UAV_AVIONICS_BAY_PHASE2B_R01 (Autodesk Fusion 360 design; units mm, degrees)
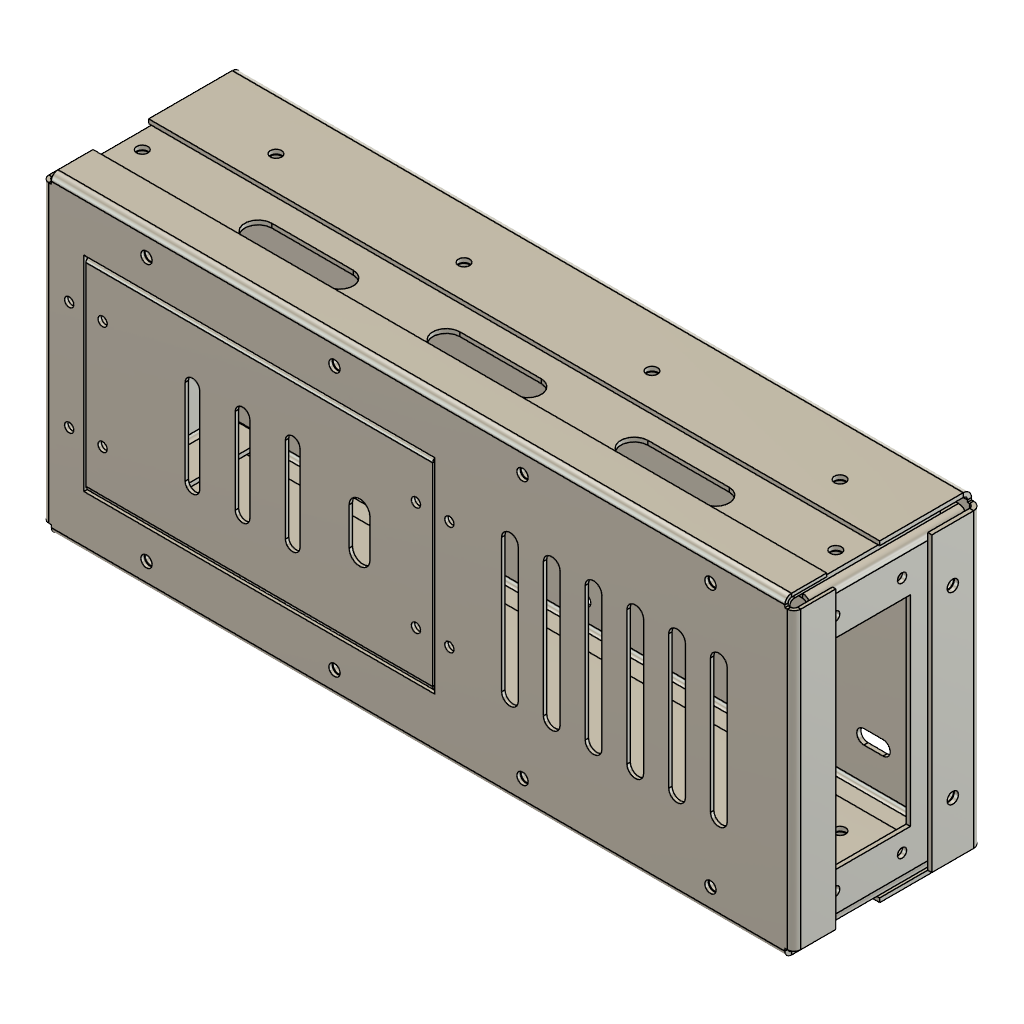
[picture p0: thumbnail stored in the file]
part number: 2026-11-23-23-53-07-860
part number: 2026-11-23-23-53-08-084
part number: 2026-11-23-23-53-08-095
part number: 2026-11-23-23-53-08-107
part number: 2026-11-23-23-53-08-119
part number: 2026-11-23-23-53-08-137
part number: 2026-11-23-23-53-08-150
part number: 2026-11-23-23-53-08-161
part number: 2026-11-23-23-53-08-171
part number: 2026-11-23-23-53-08-219
part number: 2026-11-23-23-53-09-132
part number: 2026-11-23-23-53-09-607
part number: 2026-11-23-23-53-10-129
part number: 2026-11-23-23-53-10-727
part number: 2026-11-23-23-53-11-436
part number: 2026-11-23-23-53-12-534
part number: 2026-11-23-23-53-13-223
parameter "BAY_LENGTH" = 180 comment "[Assumption] Concept avionics bay overall outer length (X)"
parameter "BAY_WIDTH" = 75 comment "[Assumption] Concept avionics bay overall outer width (Y)"
parameter "BAY_HEIGHT" = 45 comment "[Assumption] Concept avionics bay overall outer height (Z)"
parameter "TRAY_FLANGE_H" = 22 comment "[Preliminary] Base tray perimeter upward flange height"
parameter "COVER_SKIRT_H" = 10 comment "[Preliminary] Top cover downward perimeter skirt height"
parameter "FORWARD_ZONE_END_X" = 95 comment "[Preliminary] X-boundary separating battery zone and aft deck"
parameter "HATCH_LENGTH" = 92 comment "[Preliminary] Service access hatch opening length"
parameter "HATCH_WIDTH" = 54 comment "[Preliminary] Service access hatch opening width"
parameter "T_BASE_TRAY" = 1 comment "[Preliminary] Main folded base tray thickness"
parameter "T_TOP_COVER" = 0.8 comment "[Preliminary] Removable top cover thickness"
parameter "T_ACCESS_HATCH" = 0.8 comment "[Preliminary] Service access hatch thickness"
parameter "T_SIDE_RAIL" = 1 comment "[Preliminary] Left and right side support rails thickness"
parameter "T_BULKHEAD" = 1 comment "[Preliminary] Front, rear, and connector bulkheads thickness"
parameter "T_EQUIP_DECK" = 1 comment "[Preliminary] Removable internal equipment deck thickness"
parameter "T_BRACKET" = 1 comment "[Preliminary] Structural and retention brackets thickness"
parameter "T_CABLE_CH" = 0.8 comment "[Preliminary] Cable routing channel and clamp thickness"
parameter "BEND_R_1_0" = 1 comment "[Preliminary] Inside bend radius for 1.0 mm Al 5052-H32"
parameter "BEND_R_0_8" = 0.8 comment "[Preliminary] Inside bend radius for 0.8 mm Al 5052-H32"
parameter "RELIEF_W_1_0" = 1.5 comment "[Preliminary] Bend relief width for 1.0 mm sheet"
parameter "RELIEF_D_1_0" = 2.5 comment "[Preliminary] Bend relief depth for 1.0 mm sheet"
parameter "RELIEF_W_0_8" = 1.2 comment "[Preliminary] Bend relief width for 0.8 mm sheet"
parameter "RELIEF_D_0_8" = 2.1 comment "[Preliminary] Bend relief depth for 0.8 mm sheet"
parameter "HOLE_CLR_M2_0" = 2.2 comment "[Preliminary] M2.0 medium clearance hole diameter"
parameter "HOLE_CLR_M2_5" = 2.7 comment "[Preliminary] M2.5 medium clearance hole diameter"
parameter "HOLE_CLR_M3_0" = 3.4 comment "[Preliminary] M3.0 medium clearance hole diameter"
parameter "HEAD_DIA_M2_0" = 3.8 comment "[Preliminary] ISO 4762/7380 M2.0 head diameter"
parameter "HEAD_DIA_M2_5" = 4.5 comment "[Preliminary] ISO 4762/7380 M2.5 head diameter"
parameter "STANDOFF_DECK_H" = 6 comment "[Preliminary] Under-deck plenum standoff height"
parameter "STANDOFF_PCB_H" = 4 comment "[Preliminary] PCB mounting standoff height"
parameter "ISO_PAD_THICK" = 2 comment "[Preliminary] Battery elastomer isolation pad thickness"
parameter "CLR_EQUIP_WALL" = 2 comment "[Preliminary] Minimum clearance between electronics and walls"
parameter "CLR_COMPONENT" = 1.5 comment "[Preliminary] General minimum clearance between adjacent parts"
parameter "CLR_SLIP_FIT" = 0.25 comment "[Preliminary] Per-side slip clearance for nested sheet metal parts"
parameter "CLR_COVER_FIT" = 0.3 comment "[Preliminary] Per-side clearance between cover skirt and chassis"
parameter "CLR_HATCH_GAP" = 0.5 comment "[Preliminary] Perimeter gap around removable service hatch"
parameter "d37" = 2
parameter "d38" = 1
parameter "d39" = 0.8
sketch "SK_Base_Tray_Blank" plane through (0, 0, 0) normal (0, 0, 1) x axis (1, 0, 0)
  line L1 (177.5, -37.5) -> (2.5, -37.5)
  line L2 (177.5, -35) -> (177.5, -37.5)
  line L3 (180, -35) -> (177.5, -35)
  line L4 (180, 35) -> (180, -35)
  line L5 (177.5, 35) -> (180, 35)
  line L6 (177.5, 37.5) -> (177.5, 35)
  line L7 (2.5, 37.5) -> (177.5, 37.5)
  line L8 (2.5, 35) -> (2.5, 37.5)
  line L9 (0, 35) -> (2.5, 35)
  line L10 (0, -35) -> (0, 35)
  line L11 (2.5, -35) -> (0, -35)
  line L12 (2.5, -37.5) -> (2.5, -35)
face "BaseFlange1" sketch "SK_Base_Tray_Blank"
face "EdgeFlange2" FlangeHeight 22 FlangeAngle 90
face "EdgeFlange3" FlangeHeight 12 FlangeAngle 90
sketch "SK_Base_Tray_Floor_Cutouts" plane through (0, 0, 0) normal (0, 0, 1) x axis (1, 0, 0)
  line L1 (27.3, -24.3) -> (22.7, -24.3)
  line L2 (22.7, -27.7) -> (27.3, -27.7)
  line L3 (27.3, 27.7) -> (22.7, 27.7)
  line L4 (22.7, 24.3) -> (27.3, 24.3)
  line L5 (157.3, -24.3) -> (152.7, -24.3)
  line L6 (152.7, -27.7) -> (157.3, -27.7)
  line L7 (157.3, 27.7) -> (152.7, 27.7)
  line L8 (152.7, 24.3) -> (157.3, 24.3)
  line L9 (64.5, -11.5) -> (35.5, -11.5)
  line L10 (35.5, -18.5) -> (64.5, -18.5)
  line L11 (149.5, 3.5) -> (120.5, 3.5)
  line L12 (120.5, -3.5) -> (149.5, -3.5)
  arc A1 centre (27.3, -26) radius 1.7 clockwise from (27.3, -24.3) to (27.3, -27.7)
  arc A2 centre (22.7, -26) radius 1.7 clockwise from (22.7, -27.7) to (22.7, -24.3)
  arc A3 centre (27.3, 26) radius 1.7 clockwise from (27.3, 27.7) to (27.3, 24.3)
  arc A4 centre (22.7, 26) radius 1.7 clockwise from (22.7, 24.3) to (22.7, 27.7)
  arc A5 centre (157.3, -26) radius 1.7 clockwise from (157.3, -24.3) to (157.3, -27.7)
  arc A6 centre (152.7, -26) radius 1.7 clockwise from (152.7, -27.7) to (152.7, -24.3)
  arc A7 centre (157.3, 26) radius 1.7 clockwise from (157.3, 27.7) to (157.3, 24.3)
  arc A8 centre (152.7, 26) radius 1.7 clockwise from (152.7, 24.3) to (152.7, 27.7)
  circle C1 centre (102, -28.5) radius 1.35
  circle C2 centre (102, 28.5) radius 1.35
  circle C3 centre (168, -28.5) radius 1.35
  circle C4 centre (168, 28.5) radius 1.35
  circle C5 centre (14, -31) radius 1.35
  circle C6 centre (14, 1) radius 1.35
  circle C7 centre (86, -31) radius 1.35
  circle C8 centre (86, 1) radius 1.35
  circle C9 centre (13, 11) radius 1.1
  circle C10 centre (13, 27) radius 1.1
  circle C11 centre (45, 11) radius 1.1
  circle C12 centre (45, 27) radius 1.1
  circle C13 centre (57, 11) radius 1.1
  circle C14 centre (57, 27) radius 1.1
  circle C15 centre (85, 11) radius 1.1
  circle C16 centre (85, 27) radius 1.1
  arc A9 centre (64.5, -15) radius 3.5 clockwise from (64.5, -11.5) to (64.5, -18.5)
  arc A10 centre (35.5, -15) radius 3.5 clockwise from (35.5, -18.5) to (35.5, -11.5)
  arc A11 centre (149.5, 0) radius 3.5 clockwise from (149.5, 3.5) to (149.5, -3.5)
  arc A12 centre (120.5, 0) radius 3.5 clockwise from (120.5, -3.5) to (120.5, 3.5)
extrude "Extrude1" cut sketch "SK_Base_Tray_Floor_Cutouts" distance 2
work_plane "WorkPlane1" AlongDistance -37.5 ExtraOffset 0
sketch "SK_Tray_Left_Wall_Holes" plane through (0, -37.5, 0) normal (0, 1, 0) x axis (1, 0, 0)
  circle C1 centre (25, -14) radius 1.35
  circle C2 centre (70, -14) radius 1.35
  circle C3 centre (115, -14) radius 1.35
  circle C4 centre (160, -14) radius 1.35
extrude "Extrude2" cut sketch "SK_Tray_Left_Wall_Holes" distance 2
work_plane "WorkPlane2" AlongDistance 37.5 ExtraOffset 0
sketch "SK_Tray_Right_Wall_Holes" plane through (0, 37.5, 0) normal (0, 1, 0) x axis (1, 0, 0)
  circle C1 centre (25, -14) radius 1.35
  circle C2 centre (70, -14) radius 1.35
  circle C3 centre (115, -14) radius 1.35
  circle C4 centre (160, -14) radius 1.35
extrude "Extrude3" cut sketch "SK_Tray_Right_Wall_Holes" distance 2
sketch "SK_Tray_Front_Lip_Holes" plane through (0, 0, 0) normal (1, 0, 0) x axis (0, 0, -1)
  circle C1 centre (-7, -22) radius 1.35
  circle C2 centre (-7, 22) radius 1.35
extrude "Extrude4" cut sketch "SK_Tray_Front_Lip_Holes" distance 2
work_plane "WorkPlane3" AlongDistance 180 ExtraOffset 0
sketch "SK_Tray_Rear_Lip_Holes" plane through (180, 0, 0) normal (1, 0, 0) x axis (0, 0, -1)
  circle C1 centre (-7, -22) radius 1.35
  circle C2 centre (-7, 22) radius 1.35
extrude "Extrude5" cut sketch "SK_Tray_Rear_Lip_Holes" distance 2
work_plane "WorkPlane1" AlongDistance -36.35 ExtraOffset 0
sketch "SK_PDB-01-102_Left_Side_Rail_Web" plane through (0, -36.35, 0) normal (0, 1, 0) x axis (1, 0, 0)
  line L1 (177, -7) -> (3, -7)
  line L2 (177, -44) -> (177, -7)
  line L3 (3, -44) -> (177, -44)
  line L4 (3, -7) -> (3, -44)
face "BaseFlange1" sketch "SK_PDB-01-102_Left_Side_Rail_Web"
face "EdgeFlange2" FlangeHeight 9 FlangeAngle 90
sketch "SK_PDB-01-102_Left_Side_Rail_Web_Features" plane through (0, -36.35, 0) normal (0, 1, 0) x axis (1, 0, 0)
  line L1 (57.25, -34.25) -> (37.75, -34.25)
  line L2 (37.75, -27.75) -> (57.25, -27.75)
  line L3 (102.25, -34.25) -> (82.75, -34.25)
  line L4 (82.75, -27.75) -> (102.25, -27.75)
  line L5 (147.25, -34.25) -> (127.75, -34.25)
  line L6 (127.75, -27.75) -> (147.25, -27.75)
  circle C1 centre (25, -14) radius 1.35
  circle C2 centre (70, -14) radius 1.35
  circle C3 centre (115, -14) radius 1.35
  circle C4 centre (160, -14) radius 1.35
  circle C5 centre (7, -28) radius 1.35
  circle C6 centre (173, -28) radius 1.35
  arc A1 centre (57.25, -31) radius 3.25 clockwise from (57.25, -27.75) to (57.25, -34.25)
  arc A2 centre (37.75, -31) radius 3.25 clockwise from (37.75, -34.25) to (37.75, -27.75)
  arc A3 centre (102.25, -31) radius 3.25 clockwise from (102.25, -27.75) to (102.25, -34.25)
  arc A4 centre (82.75, -31) radius 3.25 clockwise from (82.75, -34.25) to (82.75, -27.75)
  arc A5 centre (147.25, -31) radius 3.25 clockwise from (147.25, -27.75) to (147.25, -34.25)
  arc A6 centre (127.75, -31) radius 3.25 clockwise from (127.75, -34.25) to (127.75, -27.75)
extrude "Extrude1" cut sketch "SK_PDB-01-102_Left_Side_Rail_Web_Features" distance 2
work_plane "WorkPlane2" AlongDistance 44 ExtraOffset 0
sketch "SK_PDB-01-102_Left_Side_Rail_Top_Holes" plane through (0, 0, 44) normal (0, 0, 1) x axis (1, 0, 0)
  circle C1 centre (25, -31.5) radius 1.35
  circle C2 centre (70, -31.5) radius 1.35
  circle C3 centre (115, -31.5) radius 1.35
  circle C4 centre (160, -31.5) radius 1.35
extrude "Extrude2" cut sketch "SK_PDB-01-102_Left_Side_Rail_Top_Holes" distance 2
work_plane "WorkPlane1" AlongDistance 36.35 ExtraOffset 0
sketch "SK_PDB-01-103_Right_Side_Rail_Web" plane through (0, 36.35, 0) normal (0, 1, 0) x axis (1, 0, 0)
  line L1 (177, -7) -> (3, -7)
  line L2 (177, -44) -> (177, -7)
  line L3 (3, -44) -> (177, -44)
  line L4 (3, -7) -> (3, -44)
face "BaseFlange2" sketch "SK_PDB-01-103_Right_Side_Rail_Web"
face "EdgeFlange3" FlangeHeight 9 FlangeAngle 90
sketch "SK_PDB-01-103_Right_Side_Rail_Web_Features" plane through (0, 36.35, 0) normal (0, 1, 0) x axis (1, 0, 0)
  line L1 (57.25, -34.25) -> (37.75, -34.25)
  line L2 (37.75, -27.75) -> (57.25, -27.75)
  line L3 (102.25, -34.25) -> (82.75, -34.25)
  line L4 (82.75, -27.75) -> (102.25, -27.75)
  line L5 (147.25, -34.25) -> (127.75, -34.25)
  line L6 (127.75, -27.75) -> (147.25, -27.75)
  circle C1 centre (25, -14) radius 1.35
  circle C2 centre (70, -14) radius 1.35
  circle C3 centre (115, -14) radius 1.35
  circle C4 centre (160, -14) radius 1.35
  circle C5 centre (7, -28) radius 1.35
  circle C6 centre (173, -28) radius 1.35
  arc A1 centre (57.25, -31) radius 3.25 clockwise from (57.25, -27.75) to (57.25, -34.25)
  arc A2 centre (37.75, -31) radius 3.25 clockwise from (37.75, -34.25) to (37.75, -27.75)
  arc A3 centre (102.25, -31) radius 3.25 clockwise from (102.25, -27.75) to (102.25, -34.25)
  arc A4 centre (82.75, -31) radius 3.25 clockwise from (82.75, -34.25) to (82.75, -27.75)
  arc A5 centre (147.25, -31) radius 3.25 clockwise from (147.25, -27.75) to (147.25, -34.25)
  arc A6 centre (127.75, -31) radius 3.25 clockwise from (127.75, -34.25) to (127.75, -27.75)
extrude "Extrude1" cut sketch "SK_PDB-01-103_Right_Side_Rail_Web_Features" distance 2
work_plane "WorkPlane2" AlongDistance 44 ExtraOffset 0
sketch "SK_PDB-01-103_Right_Side_Rail_Top_Holes" plane through (0, 0, 44) normal (0, 0, 1) x axis (1, 0, 0)
  circle C1 centre (25, 31.5) radius 1.35
  circle C2 centre (70, 31.5) radius 1.35
  circle C3 centre (115, 31.5) radius 1.35
  circle C4 centre (160, 31.5) radius 1.35
extrude "Extrude2" cut sketch "SK_PDB-01-103_Right_Side_Rail_Top_Holes" distance 2
work_plane "WorkPlane1" AlongDistance 1.15 ExtraOffset 0
sketch "SK_Front_Bulkhead_Blank" plane through (1.15, 0, 0) normal (1, 0, 0) x axis (0, 0, -1)
  line L1 (-2.5, 35.2) -> (-2.5, -35.2)
  line L2 (-39.8, 35.2) -> (-2.5, 35.2)
  line L3 (-39.8, 32.2) -> (-39.8, 35.2)
  line L4 (-42.8, 32.2) -> (-39.8, 32.2)
  line L5 (-42.8, -32.2) -> (-42.8, 32.2)
  line L6 (-39.8, -32.2) -> (-42.8, -32.2)
  line L7 (-39.8, -35.2) -> (-39.8, -32.2)
  line L8 (-2.5, -35.2) -> (-39.8, -35.2)
face "BaseFlange1" sketch "SK_Front_Bulkhead_Blank"
face "EdgeFlange2" FlangeHeight 10 FlangeAngle 90
face "EdgeFlange3" FlangeHeight 8 FlangeAngle 90
sketch "SK_Front_Bulkhead_Cutouts" plane through (1.15, 0, 0) normal (1, 0, 0) x axis (0, 0, -1)
  line L1 (-26.5, -16.5) -> (-26.5, -23.5)
  line L2 (-21.5, -23.5) -> (-21.5, -16.5)
  line L3 (-26.5, 23.5) -> (-26.5, 16.5)
  line L4 (-21.5, 16.5) -> (-21.5, 23.5)
  circle C1 centre (-7, -22) radius 1.35
  circle C2 centre (-7, 22) radius 1.35
  circle C3 centre (-24, 0) radius 5
  circle C4 centre (-24, -9) radius 1.1
  circle C5 centre (-24, 9) radius 1.1
  arc A1 centre (-24, -16.5) radius 2.5 clockwise from (-26.5, -16.5) to (-21.5, -16.5)
  arc A2 centre (-24, -23.5) radius 2.5 clockwise from (-21.5, -23.5) to (-26.5, -23.5)
  arc A3 centre (-24, 23.5) radius 2.5 clockwise from (-26.5, 23.5) to (-21.5, 23.5)
  arc A4 centre (-24, 16.5) radius 2.5 clockwise from (-21.5, 16.5) to (-26.5, 16.5)
extrude "Extrude1" cut sketch "SK_Front_Bulkhead_Cutouts" distance 2
work_plane "WorkPlane2" AlongDistance -35.2 ExtraOffset 0
sketch "SK_Front_Left_Hole" plane through (0, -35.2, 0) normal (0, 1, 0) x axis (1, 0, 0)
  circle C1 centre (7, -28) radius 1.35
extrude "Extrude2" cut sketch "SK_Front_Left_Hole" distance 2
work_plane "WorkPlane3" AlongDistance 35.2 ExtraOffset 0
sketch "SK_Front_Right_Hole" plane through (0, 35.2, 0) normal (0, 1, 0) x axis (1, 0, 0)
  circle C1 centre (7, -28) radius 1.35
extrude "Extrude3" cut sketch "SK_Front_Right_Hole" distance 2
work_plane "WorkPlane1" AlongDistance 178.85 ExtraOffset 0
sketch "SK_Rear_Bulkhead_Blank" plane through (178.85, 0, 0) normal (1, 0, 0) x axis (0, 0, -1)
  line L1 (-2.5, 35.2) -> (-2.5, -35.2)
  line L2 (-39.8, 35.2) -> (-2.5, 35.2)
  line L3 (-39.8, 32.2) -> (-39.8, 35.2)
  line L4 (-42.8, 32.2) -> (-39.8, 32.2)
  line L5 (-42.8, -32.2) -> (-42.8, 32.2)
  line L6 (-39.8, -32.2) -> (-42.8, -32.2)
  line L7 (-39.8, -35.2) -> (-39.8, -32.2)
  line L8 (-2.5, -35.2) -> (-39.8, -35.2)
face "BaseFlange2" sketch "SK_Rear_Bulkhead_Blank"
face "EdgeFlange3" FlangeHeight 10 FlangeAngle 90
face "EdgeFlange4" FlangeHeight 8 FlangeAngle 90
sketch "SK_Rear_Bulkhead_Cutouts" plane through (178.85, 0, 0) normal (1, 0, 0) x axis (0, 0, -1)
  line L1 (-16, 24) -> (-16, -24)
  line L2 (-36, 24) -> (-16, 24)
  line L3 (-36, -24) -> (-36, 24)
  line L4 (-16, -24) -> (-36, -24)
  circle C1 centre (-7, -22) radius 1.35
  circle C2 centre (-7, 22) radius 1.35
  circle C3 centre (-18, -28.5) radius 1.1
  circle C4 centre (-34, -28.5) radius 1.1
  circle C5 centre (-18, 28.5) radius 1.1
  circle C6 centre (-34, 28.5) radius 1.1
extrude "Extrude1" cut sketch "SK_Rear_Bulkhead_Cutouts" distance 2
work_plane "WorkPlane2" AlongDistance -35.2 ExtraOffset 0
sketch "SK_Rear_Left_Hole" plane through (0, -35.2, 0) normal (0, 1, 0) x axis (1, 0, 0)
  circle C1 centre (173, -28) radius 1.35
extrude "Extrude2" cut sketch "SK_Rear_Left_Hole" distance 2
work_plane "WorkPlane3" AlongDistance 35.2 ExtraOffset 0
sketch "SK_Rear_Right_Hole" plane through (0, 35.2, 0) normal (0, 1, 0) x axis (1, 0, 0)
  circle C1 centre (173, -28) radius 1.35
extrude "Extrude3" cut sketch "SK_Rear_Right_Hole" distance 2
work_plane "WorkPlane1" AlongDistance 45 ExtraOffset 0
sketch "SK_Top_Cover_Blank" plane through (0, 0, 45) normal (0, 0, 1) x axis (1, 0, 0)
  line L1 (177.8, -37.5) -> (2.2, -37.5)
  line L2 (177.8, -35.3) -> (177.8, -37.5)
  line L3 (180, -35.3) -> (177.8, -35.3)
  line L4 (180, 35.3) -> (180, -35.3)
  line L5 (177.8, 35.3) -> (180, 35.3)
  line L6 (177.8, 37.5) -> (177.8, 35.3)
  line L7 (2.2, 37.5) -> (177.8, 37.5)
  line L8 (2.2, 35.3) -> (2.2, 37.5)
  line L9 (0, 35.3) -> (2.2, 35.3)
  line L10 (0, -35.3) -> (0, 35.3)
  line L11 (2.2, -35.3) -> (0, -35.3)
  line L12 (2.2, -37.5) -> (2.2, -35.3)
face "BaseFlange2" sketch "SK_Top_Cover_Blank"
face "EdgeFlange3" FlangeHeight 10 FlangeAngle 90
face "EdgeFlange4" FlangeHeight 10 FlangeAngle 90
sketch "SK_Top_Cover_Cutouts" plane through (0, 0, 45) normal (0, 0, 1) x axis (1, 0, 0)
  line L1 (94, -24.5) -> (10, -24.5)
  line L2 (94, 24.5) -> (94, -24.5)
  line L3 (10, 24.5) -> (94, 24.5)
  line L4 (10, -24.5) -> (10, 24.5)
  line L5 (114, 16) -> (114, -16)
  line L6 (110, -16) -> (110, 16)
  line L7 (124, 16) -> (124, -16)
  line L8 (120, -16) -> (120, 16)
  line L9 (134, 16) -> (134, -16)
  line L10 (130, -16) -> (130, 16)
  line L11 (144, 16) -> (144, -16)
  line L12 (140, -16) -> (140, 16)
  line L13 (154, 16) -> (154, -16)
  line L14 (150, -16) -> (150, 16)
  line L15 (164, 16) -> (164, -16)
  line L16 (160, -16) -> (160, 16)
  circle C1 centre (25, -31.5) radius 1.35
  circle C2 centre (25, 31.5) radius 1.35
  circle C3 centre (70, -31.5) radius 1.35
  circle C4 centre (70, 31.5) radius 1.35
  circle C5 centre (115, -31.5) radius 1.35
  circle C6 centre (115, 31.5) radius 1.35
  circle C7 centre (160, -31.5) radius 1.35
  circle C8 centre (160, 31.5) radius 1.35
  circle C9 centre (6.5, -13) radius 1.1
  circle C10 centre (6.5, 13) radius 1.1
  circle C11 centre (97.5, -13) radius 1.1
  circle C12 centre (97.5, 13) radius 1.1
  arc A1 centre (112, 16) radius 2 clockwise from (110, 16) to (114, 16)
  arc A2 centre (112, -16) radius 2 clockwise from (114, -16) to (110, -16)
  arc A3 centre (122, 16) radius 2 clockwise from (120, 16) to (124, 16)
  arc A4 centre (122, -16) radius 2 clockwise from (124, -16) to (120, -16)
  arc A5 centre (132, 16) radius 2 clockwise from (130, 16) to (134, 16)
  arc A6 centre (132, -16) radius 2 clockwise from (134, -16) to (130, -16)
  arc A7 centre (142, 16) radius 2 clockwise from (140, 16) to (144, 16)
  arc A8 centre (142, -16) radius 2 clockwise from (144, -16) to (140, -16)
  arc A9 centre (152, 16) radius 2 clockwise from (150, 16) to (154, 16)
  arc A10 centre (152, -16) radius 2 clockwise from (154, -16) to (150, -16)
  arc A11 centre (162, 16) radius 2 clockwise from (160, 16) to (164, 16)
  arc A12 centre (162, -16) radius 2 clockwise from (164, -16) to (160, -16)
extrude "Extrude1" cut sketch "SK_Top_Cover_Cutouts" distance 2
work_plane "WorkPlane1" AlongDistance 45 ExtraOffset 0
sketch "SK_Access_Hatch_Blank" plane through (0, 0, 45) normal (0, 0, 1) x axis (1, 0, 0)
  line L1 (93.5, -24) -> (10.5, -24)
  line L2 (93.5, 24) -> (93.5, -24)
  line L3 (10.5, 24) -> (93.5, 24)
  line L4 (10.5, -24) -> (10.5, 24)
face "BaseFlange2" sketch "SK_Access_Hatch_Blank"
face "Hem3" HemGap 0.02 HemLength 4.5
face "Hem4" HemGap 0.02 HemLength 4.5
sketch "SK_Access_Hatch_Cutouts" plane through (0, 0, 45) normal (0, 0, 1) x axis (1, 0, 0)
  line L1 (37.75, 10.25) -> (37.75, -10.25)
  line L2 (34.25, -10.25) -> (34.25, 10.25)
  line L3 (49.75, 10.25) -> (49.75, -10.25)
  line L4 (46.25, -10.25) -> (46.25, 10.25)
  line L5 (61.75, 10.25) -> (61.75, -10.25)
  line L6 (58.25, -10.25) -> (58.25, 10.25)
  line L7 (78.5, 4.5) -> (78.5, -4.5)
  line L8 (73.5, -4.5) -> (73.5, 4.5)
  circle C1 centre (14.5, -13) radius 1.1
  circle C2 centre (14.5, 13) radius 1.1
  circle C3 centre (89.5, -13) radius 1.1
  circle C4 centre (89.5, 13) radius 1.1
  arc A1 centre (36, 10.25) radius 1.75 clockwise from (34.25, 10.25) to (37.75, 10.25)
  arc A2 centre (36, -10.25) radius 1.75 clockwise from (37.75, -10.25) to (34.25, -10.25)
  arc A3 centre (48, 10.25) radius 1.75 clockwise from (46.25, 10.25) to (49.75, 10.25)
  arc A4 centre (48, -10.25) radius 1.75 clockwise from (49.75, -10.25) to (46.25, -10.25)
  arc A5 centre (60, 10.25) radius 1.75 clockwise from (58.25, 10.25) to (61.75, 10.25)
  arc A6 centre (60, -10.25) radius 1.75 clockwise from (61.75, -10.25) to (58.25, -10.25)
  arc A7 centre (76, 4.5) radius 2.5 clockwise from (73.5, 4.5) to (78.5, 4.5)
  arc A8 centre (76, -4.5) radius 2.5 clockwise from (78.5, -4.5) to (73.5, -4.5)
extrude "Extrude1" cut sketch "SK_Access_Hatch_Cutouts" distance 2
work_plane "WorkPlane1" AlongDistance 44.2 ExtraOffset 0
sketch "SK_Retainer_Strip_Blank" plane through (0, 0, 44.2) normal (0, 0, 1) x axis (1, 0, 0)
  line L1 (18, -18) -> (3, -18)
  line L2 (18, 18) -> (18, -18)
  line L3 (3, 18) -> (18, 18)
  line L4 (3, -18) -> (3, 18)
face "BaseFlange2" sketch "SK_Retainer_Strip_Blank"
sketch "SK_Retainer_Strip_Holes" plane through (0, 0, 44.2) normal (0, 0, 1) x axis (1, 0, 0)
  circle C1 centre (6.5, -13) radius 1.1
  circle C2 centre (6.5, 13) radius 1.1
  circle C3 centre (14.5, -13) radius 1.1
  circle C4 centre (14.5, 13) radius 1.1
extrude "Extrude1" cut sketch "SK_Retainer_Strip_Holes" distance 2
copy_paste "CopyPaste1"
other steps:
create_component "CreateComponent1"
create_component "CreateComponent2"
create_component "CreateComponent3"
create_component "CreateComponent4"
create_component "CreateComponent5"
create_component "CreateComponent6"
create_component "CreateComponent7"
create_component "CreateComponent8"
create_component "CreateComponent1"
create_component "CreateComponent2"
create_component "CreateComponent3"
create_component "CreateComponent4"
create_component "CreateComponent5"
create_component "CreateComponent1"
create_component "CreateComponent2"
create_component "CreateComponent3"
